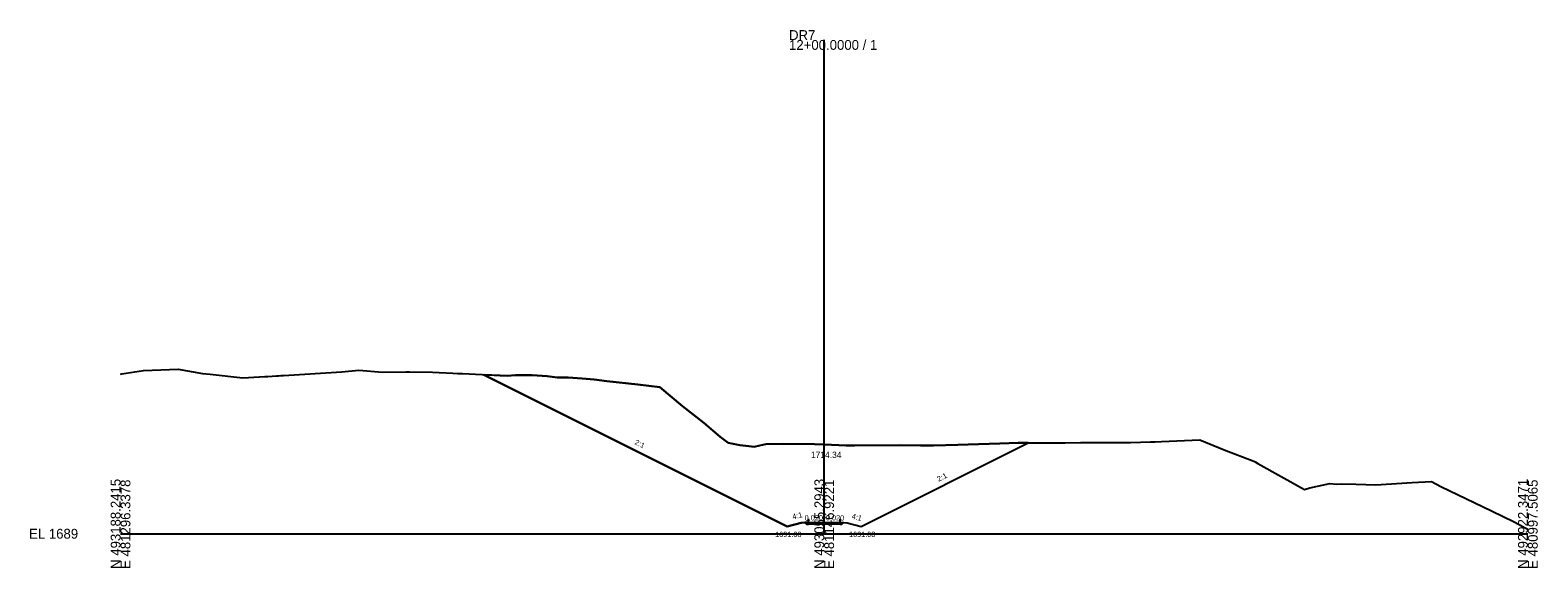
# Model space of a CAD drawing. Extents: x -26 to 403, y -10 to 4215.
# Drawn here: x -25.7 to 402.8, y 1990.3 to 2143.1 of the extents above; entities that cross this region are included whole.
import ezdxf

# ---------------------------------------------------------------- set-up
doc = ezdxf.new("R2010")
doc.units = 0
for name, color, linetype in [('Exist Cross Section Cell', 7, 'Continuous'), ('Exist XS Center Line Elevation Label', 7, 'Continuous'), ('Exist XS Ground Line', 7, 'Continuous'), ('Prop XS Ditch Slope Text', 7, 'Continuous'), ('Prop XS Ditch Standard Text', 7, 'Continuous'), ('Prop XS Dump Level', 7, 'Continuous'), ('Prop XS Earthwork Shape', 7, 'Continuous'), ('Prop XS EOT Tick Mark', 7, 'Continuous'), ('Prop XS Finish Grade', 7, 'Continuous'), ('Prop XS Finish Grade Earthwork', 7, 'Continuous'), ('Prop XS Finish Grade Pavement', 7, 'Continuous'), ('Prop XS Hydro Typical Ditch Data', 7, 'Continuous'), ('Prop XS Pvmt Edge Slope', 7, 'Continuous'), ('Prop XS SE Text', 7, 'Continuous'), ('Prop XS Shoulder Borrow Shape', 7, 'Continuous'), ('Prop XS Side Slope Text', 7, 'Continuous'), ('Prop XS Subgrade Earthwork', 7, 'Continuous')]:
    doc.layers.add(name, color=color, linetype=linetype)

msp = doc.modelspace()

# ---------------------------------------------------------------- linework, layer by layer
at = {"layer": 'Exist Cross Section Cell'}
for p, q in [((200, 2000), (200, 2140.35)), ((0, 2000), (200, 2000)), ((200, 2000), (400, 2000))]:
    msp.add_line(p, q, dxfattribs=at)
at = {"layer": 'Exist XS Ground Line'}
msp.add_lwpolyline([(0, 2045.4), (0.32, 2045.45), (4.04, 2046.03), (6.49, 2046.39), (16.36, 2046.78), (23.33, 2045.55), (25.43, 2045.33), (34.75, 2044.31), (39.46, 2044.58), (41.03, 2044.67), (41.86, 2044.72), (44.33, 2044.86), (44.86, 2044.89), (45.59, 2044.94), (46.35, 2044.98), (62.88, 2046.06), (67.7, 2046.47), (74.49, 2045.94), (81.08, 2046.03), (81.58, 2046.03), (82.13, 2046.04), (88.66, 2045.95), (94.47, 2045.67), (95.75, 2045.59), (97.18, 2045.51), (102.83, 2045.24), (107.86, 2044.95), (109.92, 2044.92), (112.23, 2045.04), (117, 2045.09), (121.25, 2044.8), (124.09, 2044.41), (127.27, 2044.38), (131.17, 2044.15), (134.64, 2043.83), (138.25, 2043.38), (147.02, 2042.47), (153.27, 2041.62), (159.68, 2036.22), (165.76, 2031.55), (170.43, 2027.59), (172.69, 2025.82), (173.63, 2025.66), (176.03, 2025.18), (178.54, 2024.87), (180.14, 2024.75), (181.67, 2025.11), (183.45, 2025.45), (188.05, 2025.56), (197.28, 2025.45), (200, 2025.34), (206.28, 2025.09), (207.24, 2025.11), (208.57, 2025.1), (221.59, 2025.14), (227.41, 2025.12), (231.08, 2025.1), (237.97, 2025.26), (243.85, 2025.47), (249.93, 2025.68), (255.13, 2025.83), (258.69, 2025.84), (262.69, 2025.86), (265.77, 2025.85), (268.52, 2025.86), (272.86, 2025.93), (277.74, 2025.94), (279.94, 2025.95), (281.91, 2025.95), (287.03, 2025.97), (292.79, 2026.09), (294.11, 2026.13), (295.89, 2026.22), (306.77, 2026.72), (313.71, 2023.9), (322.07, 2020.59), (322.45, 2020.42), (323.29, 2019.95), (336.53, 2012.61), (338.02, 2013.01), (343.74, 2014.25), (345.74, 2014.12), (347.17, 2014.23), (351.08, 2014.14), (356.76, 2013.91), (367.09, 2014.54), (372.63, 2014.89), (375.29, 2013.41), (389.7, 2006.47), (396.1, 2003.37), (399.46, 2001.61), (400, 2001.3)], dxfattribs=at)
at = {"layer": 'Prop XS Dump Level'}
for p, q in [((195.5, 2003.24), (200, 2003.33)), ((200, 2003.33), (204.5, 2003.24))]:
    msp.add_line(p, q, dxfattribs=at)
at = {"layer": 'Prop XS Earthwork Shape'}
msp.add_lwpolyline([(205.05, 2002.69), (205.52, 2003.16), (206.5, 2003.08), (210.5, 2002.08), (258.01, 2025.84), (255.13, 2025.83), (249.93, 2025.68), (243.85, 2025.47), (237.97, 2025.26), (231.08, 2025.1), (227.41, 2025.12), (221.59, 2025.14), (208.57, 2025.1), (207.24, 2025.11), (206.28, 2025.09), (200, 2025.34), (197.28, 2025.45), (188.05, 2025.56), (183.45, 2025.45), (181.67, 2025.11), (180.14, 2024.75), (178.54, 2024.87), (176.03, 2025.18), (173.63, 2025.66), (172.69, 2025.82), (170.43, 2027.59), (165.76, 2031.55), (159.68, 2036.22), (153.27, 2041.62), (147.02, 2042.47), (138.25, 2043.38), (134.64, 2043.83), (131.17, 2044.15), (127.27, 2044.38), (124.09, 2044.41), (121.25, 2044.8), (117, 2045.09), (112.23, 2045.04), (109.92, 2044.92), (107.86, 2044.95), (103.23, 2045.21), (189.5, 2002.08), (193.5, 2003.08), (194.48, 2003.16), (194.95, 2002.69), (195.5, 2002.7), (200, 2002.79), (204.5, 2002.7)], close=True, dxfattribs=at)
at = {"layer": 'Prop XS EOT Tick Mark'}
for p, q in [((195.5, 2003.24), (195.5, 2004.24)), ((204.5, 2003.24), (204.5, 2004.24))]:
    msp.add_line(p, q, dxfattribs=at)
at = {"layer": 'Prop XS Finish Grade'}
for p, q in [((195.5, 2003.24), (194.48, 2003.16)), ((204.5, 2003.24), (205.52, 2003.16))]:
    msp.add_line(p, q, dxfattribs=at)
at = {"layer": 'Prop XS Finish Grade Earthwork'}
for p, q in [((189.5, 2002.08), (103.23, 2045.21)), ((210.5, 2002.08), (258.01, 2025.84)), ((193.5, 2003.08), (189.5, 2002.08)), ((194.48, 2003.16), (193.5, 2003.08)), ((205.52, 2003.16), (206.5, 2003.08)), ((206.5, 2003.08), (210.5, 2002.08))]:
    msp.add_line(p, q, dxfattribs=at)
at = {"layer": 'Prop XS Finish Grade Pavement'}
for p, q in [((195.5, 2003.24), (200, 2003.33)), ((200, 2003.33), (204.5, 2003.24))]:
    msp.add_line(p, q, dxfattribs=at)
at = {"layer": 'Prop XS Hydro Typical Ditch Data'}
for p, q in [((189.5, 2002.08), (103.23, 2045.21)), ((210.5, 2002.08), (258.01, 2025.84)), ((193.5, 2003.08), (189.5, 2002.08)), ((206.5, 2003.08), (210.5, 2002.08))]:
    msp.add_line(p, q, dxfattribs=at)
at = {"layer": 'Prop XS Pvmt Edge Slope'}
for p, q in [((195.5, 2003.24), (194.95, 2002.69)), ((204.5, 2003.24), (205.05, 2002.69))]:
    msp.add_line(p, q, dxfattribs=at)
at = {"layer": 'Prop XS Shoulder Borrow Shape'}
for points in [[(195.5, 2003.24), (194.48, 2003.16), (194.95, 2002.69)], [(195.5, 2003.24), (194.48, 2003.16), (194.95, 2002.69)], [(204.5, 2003.24), (205.52, 2003.16), (205.05, 2002.69)], [(204.5, 2003.24), (205.52, 2003.16), (205.05, 2002.69)]]:
    msp.add_lwpolyline(points, close=True, dxfattribs=at)
at = {"layer": 'Prop XS Subgrade Earthwork'}
for p, q in [((194.95, 2002.69), (194.48, 2003.16)), ((195.5, 2002.7), (194.95, 2002.69)), ((200, 2002.79), (195.5, 2002.7)), ((204.5, 2002.7), (200, 2002.79)), ((204.5, 2002.7), (205.05, 2002.69)), ((205.05, 2002.69), (205.52, 2003.16))]:
    msp.add_line(p, q, dxfattribs=at)

# ---------------------------------------------------------------- texts
at = {"layer": 'Exist Cross Section Cell'}
for s, p in [('DR7', (190, 2140.35)), ('12+00.0000 / 1', (190, 2137.55)), ('EL 1689', (-26, 1998.6))]:
    msp.add_text(s, height=2.8, dxfattribs=at).set_placement(p)
for s, p in [('N 493188.2415', (0, 1990)), ('E 481296.3378', (2.8, 1990)), ('N 493055.2943', (200, 1990)), ('E 481146.9221', (202.8, 1990)), ('N 492922.3471', (400, 1990)), ('E 480997.5065', (402.8, 1990))]:
    msp.add_text(s, height=2.8, rotation=90, dxfattribs=at).set_placement(p)
at = {"layer": 'Exist XS Center Line Elevation Label'}
msp.add_text('1714.34', height=1.8, dxfattribs=at).set_placement((196.22, 2021.54))
at = {"layer": 'Prop XS Ditch Slope Text'}
for rotation, p in [(14.0362, (191.14, 2004.04)), (345.9638, (207.71, 2004.32))]:
    msp.add_text('4:1', height=1.5, rotation=rotation, dxfattribs=at).set_placement(p)
at = {"layer": 'Prop XS Ditch Standard Text'}
for p in [(186.06, 1999.08), (207.06, 1999.08)]:
    msp.add_text('1691.08', height=1.5, dxfattribs=at).set_placement(p)
at = {"layer": 'Prop XS Dump Level'}
for p in [(193.5, 2003.04), (206.5, 2003.04)]:
    msp.add_text('Case1', height=0.04, dxfattribs=at).set_placement(p)
at = {"layer": 'Prop XS SE Text'}
for rotation, p in [(1.1458, (194.47, 2003.73)), (358.8542, (200.48, 2003.84))]:
    msp.add_text('0.020', height=1.5, rotation=rotation, dxfattribs=at).set_placement(p)
at = {"layer": 'Prop XS Side Slope Text'}
for rotation, p in [(333.4349, (145.97, 2025.52)), (26.5651, (232.52, 2014.77))]:
    msp.add_text('2:1', height=1.5, rotation=rotation, dxfattribs=at).set_placement(p)

doc.saveas('drawing.dxf')
